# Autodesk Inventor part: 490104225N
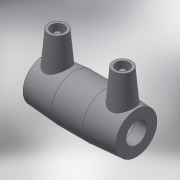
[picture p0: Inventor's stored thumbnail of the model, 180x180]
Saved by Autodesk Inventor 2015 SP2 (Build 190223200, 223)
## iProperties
Created: 2017-06
Part Number: 490104225N
Material: Generic
Description: PLASSON COUPLER 225-225
Document SubType Name: Modeling
Designer: KIM
Mass: 55.0731 g
Surface Area: 148.067 cm^2
Volume: 55.0731 cm^3
Density: 1 g/cm^3
Appearance: Default
Author: KIM
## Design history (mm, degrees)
derived "490104.ipt"
feature "Solid1::490104.ipt"
tag "TaggingFeature1"
body "Solid1"
other parameters: "d1" = 225, "d2" = 272, "d3" = 119, "d5" = 244.8, "d6" = 213.75, "d7" = 225, "d8" = 168 deg, "d10" = 47.6, "d11" = 15.86667, "d14" = 17.6296, "d15" = 119, "d16" = 119, "d17" = 213.75, "d18" = 225, "d19" = 3.52592, "d20" = 168 deg, "d22" = 255.68, "d23" = 272, "d24" = 248.0096, "d25" = 135 deg, "d27" = 135 deg, "d29" = 138, "d30" = 14, "d31" = 84, "d34" = 5 deg, "d35" = 15, "d39" = 5 deg, "d41" = 4, "d42" = 14, "d43" = 0, "d45" = 4, "d46" = 14, "d47" = 0, "d48" = 3, "d49" = 0, "d50" = 3, "d51" = 0, "d52" = 34.51, "d53" = 8.6275, "d_" = 225, "L_1" = 119, "D_" = 272, "A_" = 138, "d_2" = 12
